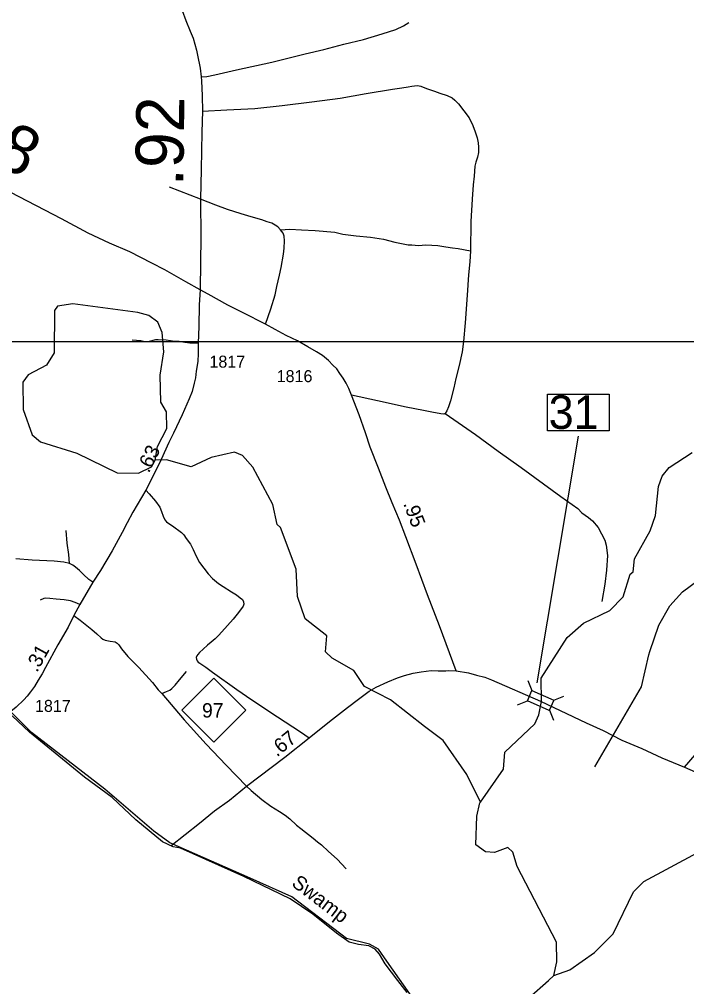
# Model space of a CAD drawing. Extents: x 2290615 to 2522933, y 819489 to 1012715.
# Drawn here: x 2457810 to 2464756, y 829858 to 839929 of the extents above; entities that cross this region are included whole.
import ezdxf

# ---------------------------------------------------------------- set-up
doc = ezdxf.new("R2010")
doc.units = 0
for name, color, linetype in [('Exist Boundary Political CountyLine', 7, 'Continuous'), ('Exist Hydrographic Creek Single Shore', 7, 'Continuous'), ('Exist Hydrographic Creek Single Shore Label', 7, 'Continuous'), ('Exist Hydrographic Misc Water Feature', 7, 'Continuous'), ('Exist Hydrographic Pond Under 1500 Sq Ft', 7, 'Continuous'), ('Exist Road Non-System Type 51', 7, 'Continuous'), ('Exist Road Primary NC Attributed', 7, 'Continuous'), ('Exist Road Primary NC Mileage Hundredths English Label', 7, 'Continuous'), ('Exist Road Primary NC Shield CELL', 7, 'Continuous'), ('Exist Road Primary NC Shield Number Label', 7, 'Continuous'), ('Exist Road Primary NC Structure Standard Bridge CELL', 7, 'Continuous'), ('Exist Road Primary NC Structure Standard Bridge Number Label', 7, 'Continuous'), ('Exist Road Secondary Mileage Hundredths English Label', 7, 'Continuous'), ('Exist Road Secondary Type 51 Attributed', 7, 'Continuous'), ('Exist Road Secondary Type 51 Number Label', 7, 'Continuous'), ('Map Preparation Inset Cut Line', 7, 'Continuous')]:
    doc.layers.add(name, color=color, linetype=linetype)

msp = doc.modelspace()

# ---------------------------------------------------------------- linework, layer by layer
at = {"layer": 'Exist Boundary Political CountyLine'}
msp.add_lwpolyline([(2461846, 829798), (2461751, 829922), (2461619, 830095), (2461560, 830196), (2461513, 830249), (2461448, 830284), (2461342, 830296), (2461242, 830320), (2461112, 830414), (2460864, 830614), (2460629, 830774), (2460146, 831004), (2459486, 831300), (2459412, 831313), (2459300, 831366), (2459023, 831596), (2458775, 831826), (2458487, 832038), (2457916, 832508), (2457735, 832677)], dxfattribs=at)
at = {"layer": 'Exist Hydrographic Creek Single Shore'}
for points in [[(2462611, 831779), (2462850, 832122), (2462864, 832300), (2463176, 832595), (2463216, 832689), (2463244, 832826), (2463243, 833071), (2463511, 833492), (2463684, 833643), (2463957, 833773), (2464096, 833916), (2464168, 834152), (2464201, 834177), (2464215, 834312), (2464377, 834604), (2464433, 834764), (2464462, 835064), (2464502, 835174), (2464575, 835265), (2464814, 835420)], [(2463375, 829974), (2463406, 830116), (2463403, 830323), (2462991, 831110), (2462947, 831259), (2462896, 831307), (2462755, 831255), (2462663, 831261), (2462562, 831336), (2462574, 831635), (2462605, 831771), (2462611, 831779)], [(2463375, 829974), (2463541, 830033), (2463796, 830214), (2463993, 830409), (2464203, 830845), (2464310, 830954), (2465144, 831402), (2465433, 831581)], [(2463112, 829743), (2463318, 829922), (2463375, 829974)]]:
    msp.add_lwpolyline(points, dxfattribs=at)
at = {"layer": 'Exist Hydrographic Misc Water Feature'}
for points in [[(2463799, 832148), (2464286, 832979), (2464364, 833313), (2464372, 833346), (2464468, 833623), (2464581, 833824), (2464712, 833968), (2464968, 834155), (2465360, 834611), (2465497, 834939), (2465656, 835424), (2465754, 835560), (2466172, 835967), (2466448, 836428), (2466580, 836532), (2466887, 836643), (2466893, 836745), (2466457, 836895), (2466322, 837027), (2466252, 837218), (2466143, 837315), (2465857, 837455)], [(2462611, 831779), (2462467, 832068), (2462222, 832420), (2462026, 832568), (2461672, 832846), (2461403, 832982), (2461292, 833149), (2461065, 833277), (2460997, 833343), (2461011, 833511), (2460784, 833689), (2460705, 833922), (2460692, 834204), (2460527, 834637), (2460493, 834669), (2460448, 834877), (2460242, 835266), (2460132, 835389), (2460048, 835422), (2459807, 835366), (2459600, 835272), (2459341, 835344), (2459224, 835339)], [(2461940, 829690), (2461635, 830124), (2461547, 830249), (2461456, 830301), (2461215, 830360), (2460645, 830792), (2460214, 830988), (2459377, 831357), (2459209, 831478), (2458700, 831915), (2457936, 832503), (2457453, 832979)]]:
    msp.add_lwpolyline(points, dxfattribs=at)
at = {"layer": 'Exist Hydrographic Pond Under 1500 Sq Ft'}
msp.add_lwpolyline([(2459224, 835339), (2459247, 835481), (2459344, 835669), (2459341, 835843), (2459282, 835942), (2459277, 836224), (2459315, 836466), (2459295, 836668), (2459252, 836775), (2459159, 836847), (2459042, 836878), (2458366, 836969), (2458208, 836942), (2458175, 836898), (2458174, 836458), (2458092, 836330), (2457902, 836227), (2457845, 836153), (2457850, 835867), (2457945, 835605), (2458030, 835530), (2458407, 835411), (2458827, 835208), (2459052, 835204), (2459184, 835272), (2459224, 835339)], dxfattribs=at)
at = {"layer": 'Exist Road Non-System Type 51'}
for points in [[(2459701, 839329), (2459761, 839335), (2459845, 839350), (2460070, 839402), (2460439, 839483), (2460785, 839571), (2460978, 839615), (2461188, 839670), (2461391, 839719), (2461588, 839778), (2461729, 839822), (2461810, 839862), (2461864, 839895)], [(2459717, 838974), (2459969, 838987), (2460260, 839001), (2460546, 839031), (2460855, 839070), (2461150, 839110), (2461419, 839158), (2461696, 839201), (2461793, 839215), (2461858, 839227), (2461896, 839234), (2461922, 839237), (2461956, 839240), (2461990, 839233), (2462049, 839208), (2462130, 839180), (2462186, 839160), (2462263, 839136), (2462314, 839111), (2462344, 839087), (2462383, 839049), (2462491, 838904), (2462529, 838824), (2462555, 838757), (2462576, 838696), (2462586, 838644), (2462589, 838598), (2462588, 838542), (2462580, 838494), (2462563, 838443), (2462552, 838401), (2462543, 838295), (2462534, 838207), (2462525, 838058), (2462510, 837826), (2462505, 837520)], [(2459717, 838974), (2459969, 838987), (2460260, 839001), (2460546, 839031), (2460855, 839070), (2461150, 839110), (2461419, 839158), (2461696, 839201), (2461793, 839215), (2461858, 839227), (2461896, 839234), (2461922, 839237), (2461956, 839240), (2461990, 839233), (2462049, 839208), (2462130, 839180), (2462186, 839160), (2462263, 839136), (2462314, 839111), (2462344, 839087), (2462383, 839049), (2462491, 838904), (2462529, 838824), (2462555, 838757), (2462576, 838696), (2462586, 838644), (2462589, 838598), (2462588, 838542), (2462580, 838494), (2462563, 838443), (2462552, 838401), (2462543, 838295), (2462534, 838207), (2462525, 838058), (2462510, 837826), (2462505, 837520)], [(2460530, 837739), (2460500, 837768), (2460474, 837786), (2460437, 837806), (2460389, 837822), (2460334, 837841), (2460223, 837872), (2460119, 837904), (2459976, 837948), (2459855, 837993), (2459696, 838056), (2459373, 838181)], [(2460374, 836755), (2460427, 836917), (2460472, 837062), (2460492, 837148), (2460517, 837265), (2460535, 837344), (2460559, 837486), (2460566, 837547), (2460570, 837623), (2460567, 837673), (2460556, 837702), (2460530, 837739)], [(2460374, 836755), (2460427, 836917), (2460472, 837062), (2460492, 837148), (2460517, 837265), (2460535, 837344), (2460559, 837486), (2460566, 837547), (2460570, 837623), (2460567, 837673), (2460556, 837702), (2460530, 837739)], [(2460530, 837739), (2460625, 837744), (2460746, 837739), (2460889, 837731), (2461094, 837713), (2461178, 837693), (2461315, 837676), (2461465, 837660), (2461600, 837642), (2461720, 837609), (2461787, 837595), (2461859, 837583), (2461895, 837580), (2461965, 837575), (2462041, 837581), (2462165, 837575), (2462248, 837561), (2462320, 837551), (2462378, 837542), (2462505, 837520)], [(2460530, 837739), (2460625, 837744), (2460746, 837739), (2460889, 837731), (2461094, 837713), (2461178, 837693), (2461315, 837676), (2461465, 837660), (2461600, 837642), (2461720, 837609), (2461787, 837595), (2461859, 837583), (2461895, 837580), (2461965, 837575), (2462041, 837581), (2462165, 837575), (2462248, 837561), (2462320, 837551), (2462378, 837542), (2462505, 837520)], [(2462505, 837520), (2462498, 837405), (2462487, 837271), (2462473, 837059), (2462450, 836770), (2462433, 836576), (2462420, 836469), (2462390, 836326), (2462355, 836189), (2462334, 836093), (2462299, 835958), (2462279, 835895), (2462260, 835855), (2462243, 835825)], [(2462505, 837520), (2462498, 837405), (2462487, 837271), (2462473, 837059), (2462450, 836770), (2462433, 836576), (2462420, 836469), (2462390, 836326), (2462355, 836189), (2462334, 836093), (2462299, 835958), (2462279, 835895), (2462260, 835855), (2462243, 835825)], [(2459671, 836557), (2459584, 836559), (2459531, 836566), (2459474, 836574), (2459429, 836576), (2459338, 836590), (2459256, 836591), (2459226, 836594), (2459162, 836574), (2459116, 836572), (2459076, 836581), (2458984, 836589)], [(2459671, 836557), (2459584, 836559), (2459531, 836566), (2459474, 836574), (2459429, 836576), (2459338, 836590), (2459256, 836591), (2459226, 836594), (2459162, 836574), (2459116, 836572), (2459076, 836581), (2458984, 836589)], [(2462243, 835825), (2462230, 835819), (2462199, 835821), (2462104, 835841), (2462018, 835858), (2461838, 835891), (2461537, 835957), (2461267, 836018)], [(2462243, 835825), (2462230, 835819), (2462199, 835821), (2462104, 835841), (2462018, 835858), (2461838, 835891), (2461537, 835957), (2461267, 836018)], [(2462243, 835825), (2462559, 835606), (2462793, 835433), (2463034, 835262), (2463267, 835095), (2463448, 834961), (2463622, 834836), (2463667, 834793), (2463734, 834742), (2463777, 834707), (2463834, 834640), (2463905, 834508), (2463920, 834456), (2463932, 834346), (2463923, 834194), (2463904, 834048), (2463874, 833867)], [(2462243, 835825), (2462559, 835606), (2462793, 835433), (2463034, 835262), (2463267, 835095), (2463448, 834961), (2463622, 834836), (2463667, 834793), (2463734, 834742), (2463777, 834707), (2463834, 834640), (2463905, 834508), (2463920, 834456), (2463932, 834346), (2463923, 834194), (2463904, 834048), (2463874, 833867)], [(2459126, 835028), (2459162, 834989), (2459226, 834913), (2459272, 834852), (2459291, 834805), (2459306, 834757), (2459325, 834718), (2459342, 834699), (2459356, 834686), (2459403, 834657), (2459497, 834586), (2459521, 834564), (2459548, 834525), (2459590, 834464), (2459621, 834411), (2459651, 834340), (2459687, 834275), (2459730, 834214), (2459774, 834155), (2459821, 834108), (2459882, 834057), (2459931, 834025), (2460017, 833970), (2460071, 833937), (2460110, 833908), (2460133, 833889), (2460143, 833865), (2460147, 833840), (2460139, 833820), (2460112, 833780), (2460079, 833735), (2460036, 833686), (2459978, 833620), (2459886, 833518), (2459849, 833481), (2459806, 833446), (2459767, 833413), (2459722, 833372), (2459687, 833337), (2459669, 833316), (2459657, 833304), (2459652, 833286), (2459653, 833269), (2459660, 833250), (2459671, 833236), (2459688, 833225), (2459751, 833184), (2459822, 833134), (2460073, 832953), (2460230, 832843), (2460498, 832668), (2460737, 832512), (2460826, 832450)], [(2459126, 835028), (2459162, 834989), (2459226, 834913), (2459272, 834852), (2459291, 834805), (2459306, 834757), (2459325, 834718), (2459342, 834699), (2459356, 834686), (2459403, 834657), (2459497, 834586), (2459521, 834564), (2459548, 834525), (2459590, 834464), (2459621, 834411), (2459651, 834340), (2459687, 834275), (2459730, 834214), (2459774, 834155), (2459821, 834108), (2459882, 834057), (2459931, 834025), (2460017, 833970), (2460071, 833937), (2460110, 833908), (2460133, 833889), (2460143, 833865), (2460147, 833840), (2460139, 833820), (2460112, 833780), (2460079, 833735), (2460036, 833686), (2459978, 833620), (2459886, 833518), (2459849, 833481), (2459806, 833446), (2459767, 833413), (2459722, 833372), (2459687, 833337), (2459669, 833316), (2459657, 833304), (2459652, 833286), (2459653, 833269), (2459660, 833250), (2459671, 833236), (2459688, 833225), (2459751, 833184), (2459822, 833134), (2460073, 832953), (2460230, 832843), (2460498, 832668), (2460737, 832512), (2460826, 832450)], [(2458332, 834263), (2458324, 834359), (2458309, 834475), (2458296, 834608)], [(2458332, 834263), (2458324, 834359), (2458309, 834475), (2458296, 834608)], [(2458440, 833837), (2458391, 833857), (2458343, 833876), (2458275, 833886), (2458192, 833893), (2458126, 833900), (2458082, 833903), (2458066, 833898), (2458025, 833883)], [(2458440, 833837), (2458391, 833857), (2458343, 833876), (2458275, 833886), (2458192, 833893), (2458126, 833900), (2458082, 833903), (2458066, 833898), (2458025, 833883)], [(2458377, 833723), (2458444, 833673), (2458566, 833576), (2458617, 833531), (2458661, 833490), (2458680, 833477), (2458702, 833467), (2458754, 833454), (2458808, 833447), (2458829, 833433), (2458844, 833418), (2458859, 833396), (2458874, 833374), (2458939, 833296), (2459054, 833180), (2459195, 833025), (2459255, 832949), (2459293, 832909)], [(2458377, 833723), (2458444, 833673), (2458566, 833576), (2458617, 833531), (2458661, 833490), (2458680, 833477), (2458702, 833467), (2458754, 833454), (2458808, 833447), (2458829, 833433), (2458844, 833418), (2458859, 833396), (2458874, 833374), (2458939, 833296), (2459054, 833180), (2459195, 833025), (2459255, 832949), (2459293, 832909)], [(2459293, 832909), (2459343, 832930), (2459375, 832944), (2459398, 832961), (2459433, 832998), (2459476, 833051), (2459550, 833138)], [(2459293, 832909), (2459343, 832930), (2459375, 832944), (2459398, 832961), (2459433, 832998), (2459476, 833051), (2459550, 833138)], [(2459293, 832909), (2459527, 832638), (2459754, 832383), (2459962, 832163), (2460175, 831945), (2460222, 831902), (2460335, 831807), (2460427, 831739), (2460518, 831682), (2460577, 831644), (2460624, 831607), (2460696, 831541), (2460741, 831504), (2460869, 831405), (2460913, 831367), (2460955, 831334), (2461027, 831267), (2461117, 831184), (2461212, 831085)], [(2464733, 832145), (2464845, 832273)]]:
    msp.add_lwpolyline(points, dxfattribs=at)
at = {"layer": 'Exist Road Primary NC Attributed'}
for points in [[(2459388, 831324), (2459684, 831559), (2459842, 831690), (2459996, 831799), (2460175, 831945), (2460573, 832246), (2460826, 832450), (2461038, 832619), (2461226, 832764), (2461339, 832850), (2461451, 832933), (2461526, 832976), (2461647, 833031), (2461746, 833074), (2461821, 833099), (2461910, 833123), (2461993, 833135), (2462096, 833149), (2462169, 833148), (2462248, 833146), (2462281, 833149), (2462356, 833145)], [(2462356, 833145), (2462486, 833127), (2462569, 833103), (2462655, 833080), (2462725, 833054), (2463235, 832831)], [(2463235, 832831), (2463710, 832605), (2463886, 832526), (2464080, 832426), (2464290, 832339), (2464497, 832242), (2464733, 832145), (2464989, 832034)]]:
    msp.add_lwpolyline(points, dxfattribs=at)
at = {"layer": 'Exist Road Primary NC Shield CELL'}
msp.add_lwpolyline([(2459503, 832737), (2459836, 833070), (2460169, 832737), (2459836, 832404)], close=True, dxfattribs=at)
at = {"layer": 'Exist Road Primary NC Structure Standard Bridge CELL'}
for p, q in [((2463104, 833046), (2463146, 832940)), ((2463373, 832841), (2463478, 832882)), ((2462994, 832793), (2463100, 832834)), ((2463328, 832737), (2463369, 832632))]:
    msp.add_line(p, q, dxfattribs=at)
msp.add_lwpolyline([(2463146, 832940), (2463373, 832841), (2463327, 832735), (2463100, 832834)], close=True, dxfattribs=at)
at = {"layer": 'Exist Road Primary NC Structure Standard Bridge Number Label'}
msp.add_line((2463199, 833021), (2463629, 835590), dxfattribs=at)
msp.add_lwpolyline([(2463307, 836027), (2463951, 836027), (2463951, 835645), (2463307, 835645)], close=True, dxfattribs=at)
at = {"layer": 'Exist Road Secondary Type 51 Attributed'}
for points in [[(2459504, 840022), (2459544, 839917), (2459588, 839805), (2459619, 839734), (2459654, 839607), (2459666, 839556), (2459691, 839422), (2459701, 839329), (2459705, 839290), (2459712, 839134), (2459717, 838974), (2459709, 838754), (2459703, 838366), (2459696, 838056), (2459698, 837656), (2459696, 837402), (2459691, 837113)], [(2459691, 837113), (2459543, 837198), (2459325, 837320), (2459190, 837390), (2458960, 837510), (2458748, 837600), (2458526, 837704), (2458248, 837851), (2457723, 838125), (2457325, 838332), (2456744, 838628), (2456435, 838782), (2456257, 838894), (2456079, 839025), (2455933, 839133), (2455708, 839288), (2455436, 839493), (2455274, 839620), (2455102, 839751), (2454998, 839835), (2454884, 839925), (2454789, 839989)], [(2459691, 837113), (2459681, 836958), (2459677, 836733), (2459671, 836557), (2459671, 836452), (2459669, 836366), (2459652, 836265), (2459644, 836196), (2459631, 836141), (2459608, 836053), (2459577, 835977), (2459504, 835813), (2459416, 835620), (2459366, 835523), (2459288, 835348), (2459214, 835198), (2459126, 835028), (2458993, 834799), (2458934, 834687), (2458880, 834588), (2458775, 834397), (2458655, 834192), (2458576, 834068)], [(2462356, 833145), (2462182, 833616), (2462060, 833939), (2461942, 834256), (2461832, 834540), (2461766, 834715), (2461690, 834896), (2461624, 835059), (2461547, 835257), (2461462, 835476), (2461412, 835625), (2461347, 835813), (2461267, 836018), (2461240, 836086), (2461213, 836141), (2461181, 836195), (2461146, 836242), (2461114, 836290), (2461075, 836330), (2461027, 836379), (2460964, 836429), (2460905, 836469), (2460813, 836520), (2460707, 836581), (2460586, 836639), (2460474, 836701), (2460374, 836755), (2460140, 836873), (2459982, 836955), (2459776, 837067), (2459691, 837113)], [(2458576, 834068), (2458533, 834098), (2458478, 834151), (2458435, 834192), (2458396, 834227), (2458368, 834248), (2458332, 834263), (2458272, 834278), (2458172, 834287), (2457944, 834297), (2457775, 834311)], [(2458576, 834068), (2458440, 833837), (2458377, 833723), (2458317, 833602), (2458212, 833416), (2458082, 833180), (2458049, 833115), (2458006, 833049), (2457966, 832985), (2457926, 832928), (2457892, 832883), (2457856, 832843), (2457778, 832769), (2457703, 832708)]]:
    msp.add_lwpolyline(points, dxfattribs=at)
at = {"layer": 'Map Preparation Inset Cut Line'}
msp.add_lwpolyline([(2451196, 836576), (2482666, 836576), (2482666, 823594), (2451196, 823594)], close=True, dxfattribs=at)

# ---------------------------------------------------------------- texts
at = {"layer": 'Exist Hydrographic Creek Single Shore Label'}
msp.add_text('Swamp', height=150, rotation=322.7354, dxfattribs=at).set_placement((2460634, 830915))
at = {"layer": 'Exist Road Primary NC Mileage Hundredths English Label'}
msp.add_text('.67', height=150, rotation=38.7565, dxfattribs=at).set_placement((2460491, 832245))
at = {"layer": 'Exist Road Primary NC Shield Number Label'}
msp.add_text('97', height=150, dxfattribs=at).set_placement((2459712, 832660))
at = {"layer": 'Exist Road Primary NC Structure Standard Bridge Number Label'}
msp.add_text('31', height=350, dxfattribs=at).set_placement((2463320, 835665))
at = {"layer": 'Exist Road Secondary Mileage Hundredths English Label'}
for s, height, rotation, p in [('1.08', 500, 332.9653, (2456700, 838859)), ('.92', 500, 89.1185, (2459515, 838192)), ('.63', 150, 63.6681, (2459158, 835198)), ('.95', 150, 290.7743, (2461804, 834887)), ('.31', 150, 61.1382, (2457994, 833123))]:
    msp.add_text(s, height=height, rotation=rotation, dxfattribs=at).set_placement(p)
at = {"layer": 'Exist Road Secondary Type 51 Number Label'}
for s, p in [('1817', (2459789, 836303)), ('1816', (2460489, 836152)), ('1817', (2457973, 832719))]:
    msp.add_text(s, height=125, rotation=360, dxfattribs=at).set_placement(p)

doc.saveas('drawing.dxf')
